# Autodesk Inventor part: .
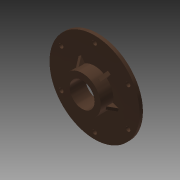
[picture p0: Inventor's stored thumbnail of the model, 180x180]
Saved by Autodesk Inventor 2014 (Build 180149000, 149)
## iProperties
Created: 2002-09
Part Number: .
Document SubType Name: Modeling
Description: holder_out.ipt.
Density: 1 g/cm^3
Material: Generic
Appearance: Bronze - Satin
ProtocolID: P00021208182929365
Protocol: P00021208182929365<@PID>[Files]<@EL>Output=C:\DOCUME~1\ADMINI~1\LOCALS~1\Temp\P00021208182929365.BMP<@EL>DataFile=SpiData|userpart<@EL>[LinksFrom]<@EL>DIAM_OUT=
Control State: 0
Master: False
Checked Out: False
Shininess: 64.0
Length Units: 11269
Angle Units: 11279
Time Units: 11290
Mass Units: 11283
Length Display Precision: 3
Angle Display Precision: 2
Density: 0.0
Volumn: 0.0
Area: 0.0
PropertySet Name: Model Information
Author: PaulN
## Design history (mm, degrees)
sketch "Sketch1"
  geometry: C1 r 108.5 at (0, -59.441); C2 r 30 at (0, -59.441)
  constraints: 2 centre point, 1 coincident
  dimensions: "d0" = 60 diameter of C2; "DIAM_OUT" = 217 diameter of C1
extrude "Extrusion1" new body sketch "Sketch1" distance "d1" = 8; taper "d2" = 0 deg
sketch "Sketch2"
  geometry: C1 r 30 at (0, 0) reference; C2 r 108.5 at (0, 0) reference; C3 r 5.5 at (0, 93)
  constraints: 1 centre point, 1 vertical alignment
  dimensions: "d19" = 11 diameter of C3; "d20" = 10 dimension on C2 C3
extrude "Extrusion2" cut sketch "Sketch2" stored distance "d3" = 10; taper "d4" = 0 deg
pattern_circular "Circular Pattern1" dims angle "d7" = 360 deg
sketch "Sketch3"
  geometry: L1 (0, 0)-(0, -45); C1 r 30 at (0, 0) reference; C2 r 108.5 at (0, 0) reference
  constraints: 2 end point, 1 vertical, 1 vertical alignment, 2 other
  dimensions: "d8" = 15 dimension on C1
extrude "Extrusion3" join sketch "Sketch3" distance "d9" = 30; taper "d10" = 0 deg
workaxis "Work Axis1"
workplane "Work Plane1"
sketch "Sketch4"
  geometry: L1 (45, 0)-(45, 30) reference; L2 (45, 15)-(60, 0); L3 (-108.5, 0)-(108.5, 0) reference; L4 (30, -8)-(30, 30) reference; L5 (45, 15)-(30, 15); L6 (60, 0)-(30, 0)
  constraints: 6 end point, 4 point on line, 1 midpoint, 1 perpendicular
  dimensions: "d11" = 45 deg angle of L1 L2
extrude "Extrusion4" join sketch "Sketch4" stored distance "d12" = 8; taper "d13" = 0 deg
pattern_circular "Circular Pattern2" dims angle "d16" = 360 deg
body "Solid1"
